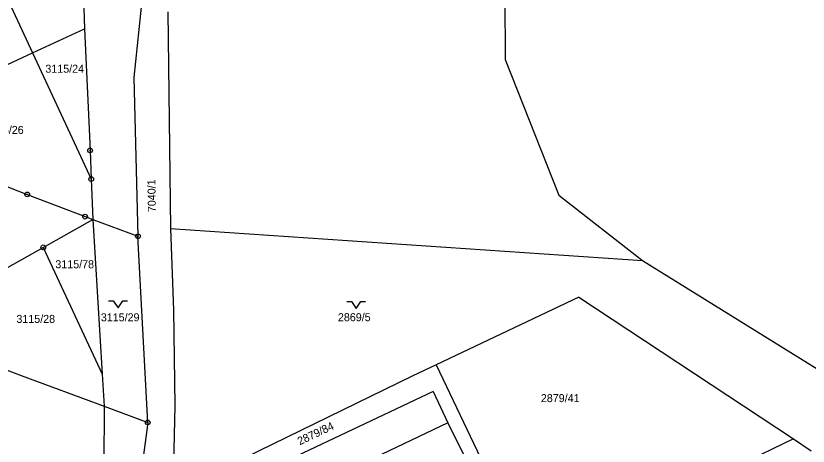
# Model space of a CAD drawing. Extents: x -593183 to -588034, y -1130415 to -1124994.
# Drawn here: x -591741.6 to -591573.4, y -1127794.8 to -1127703.4 of the extents above; entities that cross this region are included whole.
import ezdxf

# ---------------------------------------------------------------- set-up
doc = ezdxf.new("R2010")
doc.units = 0
for name, color, linetype in [('Vrstva 1', 7, 'Continuous'), ('Vrstva 18', 7, 'Continuous'), ('Vrstva 24', 7, 'Continuous'), ('Vrstva 25', 7, 'Continuous'), ('Vrstva 4', 7, 'Continuous')]:
    doc.layers.add(name, color=color, linetype=linetype)

msp = doc.modelspace()

# ---------------------------------------------------------------- linework, layer by layer
at = {"layer": 'Vrstva 1'}
for p, q in [((-591637.85, -1127683.63), (-591637.72, -1127712.65)), ((-591713.65, -1127687.91), (-591716.55, -1127716.45)), ((-591709.33, -1127702.55), (-591708.78, -1127748.59)), ((-591738.07, -1127711.25), (-591727.01, -1127706.12)), ((-591727.01, -1127706.12), (-591725.85, -1127731.96)), ((-591749.86, -1127716.73), (-591738.07, -1127711.25)), ((-591637.72, -1127712.65), (-591626.27, -1127741.45)), ((-591716.55, -1127716.45), (-591715.69, -1127750.2)), ((-591773.82, -1127728.04), (-591739.19, -1127741.33)), ((-591725.85, -1127731.96), (-591725.61, -1127738.07)), ((-591725.61, -1127738.07), (-591725.28, -1127746.65)), ((-591739.19, -1127741.33), (-591726.92, -1127746.04)), ((-591626.27, -1127741.45), (-591608.56, -1127755.32)), ((-591735.8, -1127752.56), (-591725.28, -1127746.65)), ((-591726.92, -1127746.04), (-591725.28, -1127746.65)), ((-591725.28, -1127746.65), (-591715.69, -1127750.2)), ((-591725.28, -1127746.65), (-591723.3, -1127779.49)), ((-591708.78, -1127748.59), (-591608.56, -1127755.32)), ((-591708.78, -1127748.59), (-591708.13, -1127765.9)), ((-591713.61, -1127789.74), (-591715.69, -1127750.2)), ((-591753.25, -1127762.37), (-591735.8, -1127752.56)), ((-591735.8, -1127752.56), (-591723.3, -1127779.49)), ((-591608.56, -1127755.32), (-591564.77, -1127782.51)), ((-591622.03, -1127763.13), (-591652.36, -1127777.48)), ((-591622.03, -1127763.13), (-591576.44, -1127793.22)), ((-591708.13, -1127765.9), (-591707.84, -1127786.14)), ((-591743.44, -1127778.66), (-591740.48, -1127779.77)), ((-591652.36, -1127777.48), (-591657.47, -1127779.9)), ((-591652.36, -1127777.48), (-591639.59, -1127804.19)), ((-591740.48, -1127779.77), (-591722.89, -1127786.3)), ((-591723.3, -1127779.49), (-591722.89, -1127786.3)), ((-591657.47, -1127779.9), (-591705.31, -1127803.24)), ((-591652.96, -1127783.2), (-591702.98, -1127806.77)), ((-591652.96, -1127783.2), (-591649.84, -1127789.81)), ((-591722.89, -1127786.3), (-591722.99, -1127803.69)), ((-591722.89, -1127786.3), (-591713.61, -1127789.74)), ((-591707.84, -1127786.14), (-591708.19, -1127802.01)), ((-591713.61, -1127789.74), (-591716, -1127808.09)), ((-591649.84, -1127789.81), (-591693.58, -1127810.58)), ((-591649.84, -1127789.81), (-591646.29, -1127797.15)), ((-591576.44, -1127793.22), (-591596.62, -1127802.96)), ((-591576.44, -1127793.22), (-591572.73, -1127795.78))]:
    msp.add_line(p, q, dxfattribs=at)
for points in [[(-591782.49, -1127646.49), (-591770.69, -1127641.03), (-591738.07, -1127711.25)], [(-591738.07, -1127711.25), (-591727.81, -1127733.34), (-591725.61, -1127738.07)]]:
    msp.add_lwpolyline(points, dxfattribs=at)
at = {"layer": 'Vrstva 24'}
for centre, radius in [((-591725.85, -1127731.96), 0.5), ((-591725.85, -1127731.96), 0.0327), ((-591725.61, -1127738.07), 0.5), ((-591725.61, -1127738.07), 0.0327), ((-591739.19, -1127741.33), 0.5), ((-591739.19, -1127741.33), 0.0327), ((-591726.92, -1127746.04), 0.5), ((-591726.92, -1127746.04), 0.0327), ((-591715.69, -1127750.2), 0.5), ((-591715.69, -1127750.2), 0.0327), ((-591735.8, -1127752.56), 0.5), ((-591735.8, -1127752.56), 0.0327), ((-591713.61, -1127789.74), 0.5), ((-591713.61, -1127789.74), 0.0327)]:
    msp.add_circle(centre, radius, dxfattribs=at)
at = {"layer": 'Vrstva 25'}
for points in [[(-591721.92, -1127763.94), (-591720.92, -1127763.94), (-591719.92, -1127765.44), (-591718.92, -1127763.94), (-591717.92, -1127763.94)], [(-591671.35, -1127764.05), (-591670.35, -1127764.05), (-591669.35, -1127765.55), (-591668.35, -1127764.05), (-591667.35, -1127764.05)]]:
    msp.add_lwpolyline(points, dxfattribs=at)
at = {"layer": 'Vrstva 4'}
msp.add_line((-591728.37, -1127671.87), (-591727.01, -1127706.12), dxfattribs=at)

# ---------------------------------------------------------------- texts
at = {"layer": 'Vrstva 18'}
for s, p in [('3115/24', (-591735.35, -1127715.47)), ('3115/26', (-591748.17, -1127728.47)), ('3115/78', (-591733.23, -1127757)), ('3115/28', (-591741.5, -1127768.61)), ('3115/29', (-591723.57, -1127768.27)), ('2869/5', (-591673.22, -1127768.25)), ('2879/41', (-591630.12, -1127785.43))]:
    msp.add_text(s, height=1.7, dxfattribs=at).set_placement(p)
for s, rotation, p in [('7040/1', 91.0858, (-591711.86, -1127745.07)), ('2879/84', 25.3462, (-591681.32, -1127794.61))]:
    msp.add_text(s, height=1.7, rotation=rotation, dxfattribs=at).set_placement(p)

doc.saveas('drawing.dxf')
